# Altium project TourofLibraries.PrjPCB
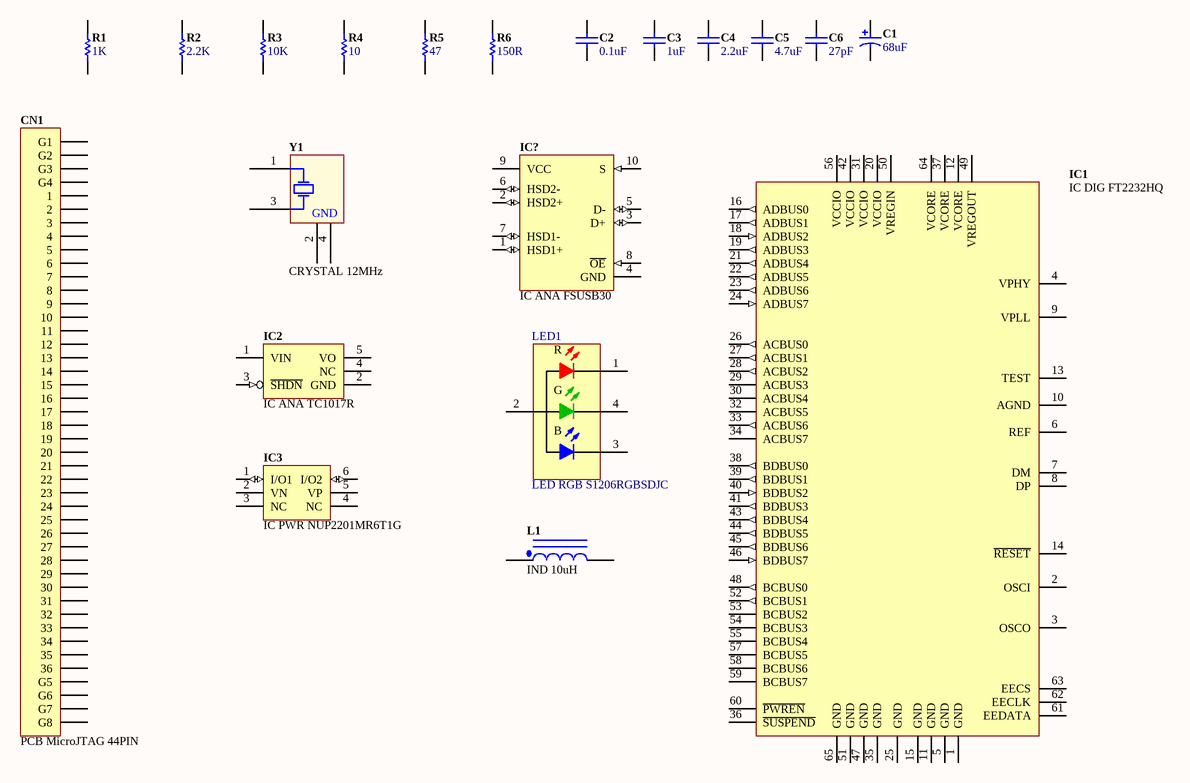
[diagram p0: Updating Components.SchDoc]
1 sheet, 20 parts. Net scope: global (net labels, ports and power ports of the same name join across sheets).

## Sheet Updating Components.SchDoc
size B

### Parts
C1  value 68uF  [CAPC3528-STAR]  (hidden comment: CAP 68uF 6.3V)
C2  value 0.1uF  [CAPC1005-STAR]  (hidden comment: CAP .1uF 16V)
C3  value 1uF  [CAPC1005-STAR]  (hidden comment: CAP 1uF 16V)
C4  value 2.2uF  [CAPC1005-STAR]  (hidden comment: CAP 2.2uF 16V)
C5  value 4.7uF  [CAPC1005-STAR]  (hidden comment: CAP 4.7uF 4V)
C6  value 27pF  [CAPC1005-STAR]  (hidden comment: CAP 27pf 50V)
CN1  PCB MicroJTAG 44PIN  [MODEDGE-2MMX44]
IC1  IC DIG FT2232HQ  [QFN-64]
IC2  IC ANA TC1017R  [SOT-25]
IC3  IC PWR NUP2201MR6T1G  [ONSC-TSOP-6_V]
IC?  IC ANA FSUSB30  [MLP10A]
L1  IND 10uH  [3216]
LED1  LED RGB S1206RGBSDJC  [SANT-LED1206-2_V]
R1  value 1K  [RESC1005-STAR]  (hidden comment: RES 1K 1% 1/4W)
R2  value 2.2K  [RESC1005-STAR]  (hidden comment: RES 2.2K 1% 1/4W)
R3  value 10K  [RESC1005-STAR]  (hidden comment: RES 10K 1% 1/4W)
R4  value 10  [RESC1005-STAR]  (hidden comment: RES 10R 1% 1/4W)
R5  value 47  [RESC1005-STAR]  (hidden comment: RES 47R 1% 1/4W)
R6  value 150R  [RESC1005-STAR]  (hidden comment: RES 150R 1% 1/4W)
Y1  CRYSTAL 12MHz  [OSCN17P250X200X80-4]

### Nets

Not connected (* = marked no-connect by the designer): C1 1 2; C2 1 2; C3 1 2; C4 1 2; C5 1 2; C6 1 2; CN1 1 2 3 4 5 6 7 8 9 10 11 12 13 14 15 16 17 18 19 20 21 22 23 24 25 26 27 28 29 30 31 32 33 34 35 36 G1 G2 G3 G4 G5 G6 G7 G8; IC1 1(GND) 2(OSCI) 3(OSCO) 4(VPHY) 5(GND) 6(REF) 7(DM) 8(DP) 9(VPLL) 10(AGND) 11(GND) 12(VCORE) 13(TEST) 14(~{RESET}) 15(GND) 16(ADBUS0) 17(ADBUS1) 18(ADBUS2) 19(ADBUS3) 20(VCCIO) 21(ADBUS4) 22(ADBUS5) 23(ADBUS6) 24(ADBUS7) 25(GND) 26(ACBUS0) 27(ACBUS1) 28(ACBUS2) 29(ACBUS3) 30(ACBUS4) 31(VCCIO) 32(ACBUS5) 33(ACBUS6) 34(ACBUS7) 35(GND) 36(~{SUSPEND}) 37(VCORE) 38(BDBUS0) 39(BDBUS1) 40(BDBUS2) 41(BDBUS3) 42(VCCIO) 43(BDBUS4) 44(BDBUS5) 45(BDBUS6) 46(BDBUS7) 47(GND) 48(BCBUS0) 49(VREGOUT) 50(VREGIN) 51(GND) 52(BCBUS1) 53(BCBUS2) 54(BCBUS3) 55(BCBUS4) 56(VCCIO) 57(BCBUS5) 58(BCBUS6) 59(BCBUS7) 60(~{PWREN}) 61(EEDATA) 62(EECLK) 63(EECS) 64(VCORE) 65(GND); IC2 1(VIN) 2(GND) 3(~{SHDN}) 4(NC) 5(VO); IC3 1(I/O1) 2(VN) 3(NC) 4(NC) 5(VP) 6(I/O2); IC? 1(HSD1+) 2(HSD2+) 3(D+) 4(GND) 5(D-) 6(HSD2-) 7(HSD1-) 8(~{OE}) 9(VCC) 10(S); L1 1 2; LED1 1(R) 2(A2) 3(B) 4(G); R1 1 2; R2 1 2; R3 1 2; R4 1 2; R5 1 2; R6 1 2; Y1 1(X1) 2(GND) 3(X2) 4(GND)

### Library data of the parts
C1 = CPN-CAP-0005: CAP,Ceramic,68uF,20%,6.3V,3.5x2.8mm B-Case; Manufacturer Name: AVX; Manufacturer Part: TPSB686K006R0500; Tolerance: 10%
C2 = CPN-CAP-0000: CAP,Ceramic,0.1uF,10%,16V,1005; Manufacturer Name: AVX; Manufacturer Part: 01016D101KAT2A
C3 = CPN-CAP-0001: CAP,Ceramic,1uF,10%,16V,1005; Manufacturer Name: Kemet; Manufacturer Part: C0402C103K4RACTU; TempCoef: X7R
C4 = CPN-CAP-0002: CAP,Ceramic,2.2uF,10%,16V,1005; Manufacturer Name: TDK Corporation; Manufacturer Part: C1005X6S1C225K050BC; TempCoef: X6S
C5 = CPN-CAP-0003: CAP,Ceramic,27pF,5%,50V,1005; Manufacturer Name: TDK; Manufacturer Part: C1005X6S0G475M050BC; Tolerance: 20%
C6 = CPN-CAP-0004: CAP,Ceramic,04.7uF,20%,16V,1005; Manufacturer Name: AVX; Manufacturer Part: 04025A270JAT2A; Tolerance: 5%
CN1 = CPN-CON-0000: PCB,DT05,MircoJTAG,Altium,44Pin,TH
IC1 = CPN-IC-00004: IC,Digital,FT2232H,DUAL HIGH SPEED USB TO MULTIPURPOSE UART/FIFO IC; Manufacturer Name: FTDI; Manufacturer Part: FT2232HQ-TRAY
IC2 = CPN-IC-00002: IC,Analog,XC6220B331MR-G,High Current High Speed LDO Regulator; Manufacturer Name: Torex Semiconductor Ltd
IC3 = CPN-IC-00005: IC,Power,NUP2201MR6T1G,ESD Protection Diodes with Low Clamping Voltage,TSOP-6; Manufacturer Name: ON Semiconductor
IC? = CPN-IC-00001: IC,Analog,FSUB30,Low-Power, Two-Port, High-Speed USB2.0 Switch; Manufacturer Name: Fairchild Semiconductor; Manufacturer Part: FSUSB30L10X
L1 = CPN-IND-0000: Inductor,10uH,450mA,0.3R,3216; Manufacturer Name: VISHAY DALE; Manufacturer Part: ILB1206ER301V
LED1 = CPN-LED-0000: LED,S1206RGBSDJC,Sansen LED RGB,SMD; Manufacturer Name: Everlight; Manufacturer Part: 15-13D/R6GHBHC-A01/2T
R1 = CPN-RES-0000: Resistor,10R,1%,125mW,1005; Manufacturer Name: KOA Speer; Manufacturer Part: SG73P1ETTP1001F; TempCoef: 200 PPM / C
R2 = CPN-RES-0001: Resistor,47R,1%,125mW,1005; Manufacturer Name: KOA Speer; Manufacturer Part: SG73P1ETTP2201F; TempCoef: 200 PPM / C
R3 = CPN-RES-0002: Resistor,1K,1%,125mW,1005; Manufacturer Name: KOA Speer; Manufacturer Part: SG73P1ETTP1002F; TempCoef: 200 PPM / C
R4 = CPN-RES-0003: Resistor,2.2K,1%,125mW,1005; Manufacturer Name: KOA Speer; Manufacturer Part: SG73P1ETTP10R0F; TempCoef: 200 PPM / C
R5 = CPN-RES-0004: Resistor,150R,1%,125mW,1005; Manufacturer Name: KOA Speer; Manufacturer Part: SG73S1ETTP47R0F; TempCoef: 200 PPM / C
R6 = CPN-RES-0005: Resistor,10K,1%,125mW,1005; Manufacturer Name: KOA Speer; Manufacturer Part: SG73P1ETTP1500F; TempCoef: 200 PPM / C
Y1 = CPN-IC-00000: IC,Analog,Crystal,12.000MHz,30ppm,10pF; Manufacturer Name: TXC; Manufacturer Part: 7B-12.000MEEQ-T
